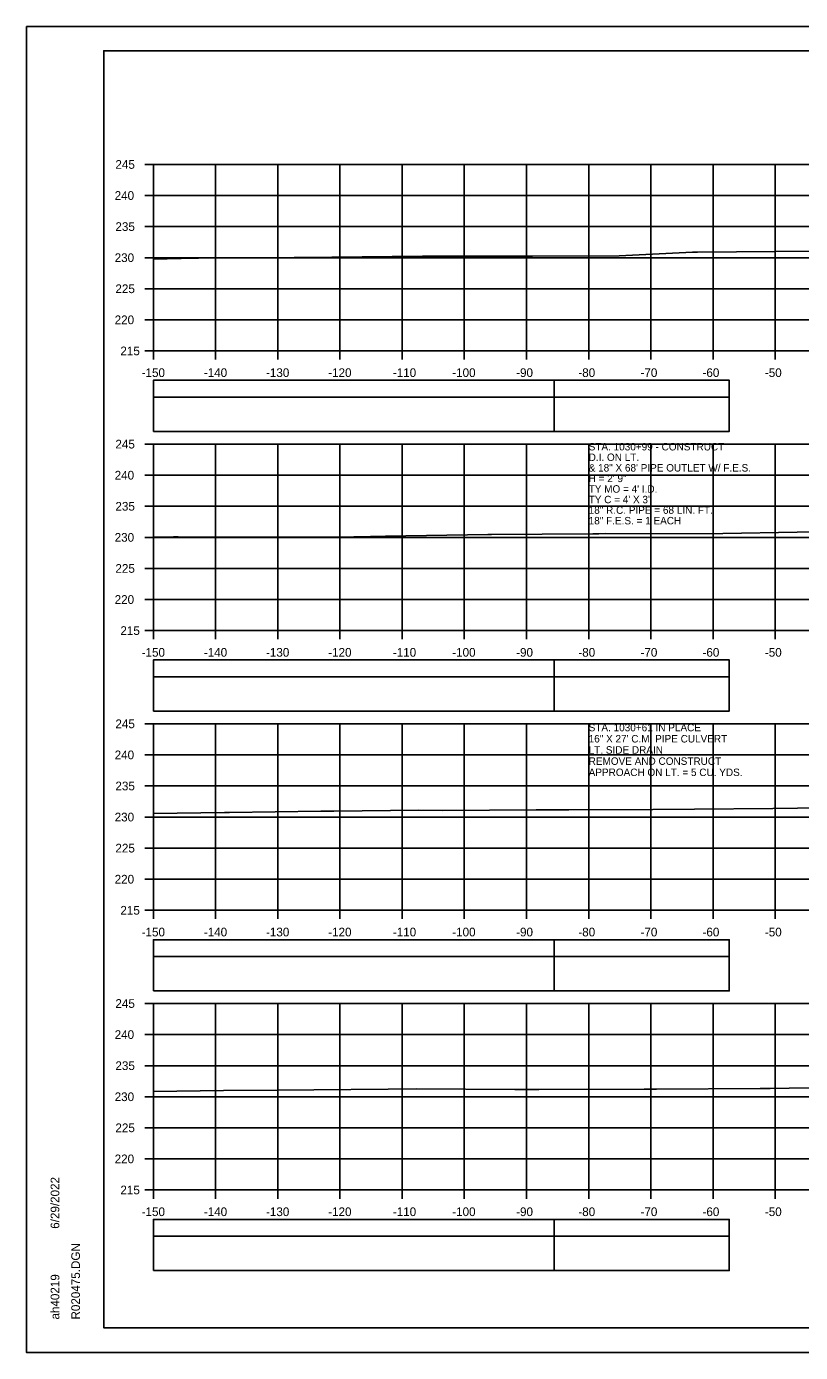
# Model space of a CAD drawing. Extents: x 1386544 to 1388153, y 379785 to 390999.
# Drawn here: x 1387177.5 to 1387301.9, y 385001.6 to 385214.9 of the extents above; entities that cross this region are included whole.
import ezdxf

# ---------------------------------------------------------------- set-up
doc = ezdxf.new("R2010")
doc.units = 0
for name, color, linetype in [('R_Axis', 7, 'Continuous'), ('R_Axis Annot', 7, 'Continuous'), ('R_Border', 7, 'Continuous'), ('R_Drive', 7, 'Continuous'), ('R_Exist Surface', 7, 'Continuous'), ('R_Grid', 7, 'Continuous'), ('R_No Plot', 7, 'Continuous'), ('R_Striping', 7, 'Continuous'), ('R_Water Annot', 7, 'Continuous')]:
    doc.layers.add(name, color=color, linetype=linetype)

msp = doc.modelspace()

# ---------------------------------------------------------------- linework, layer by layer
at = {"layer": 'R_Axis'}
for p, q in [((1387196.48, 385192.7), (1387197.88, 385192.7)), ((1387197.88, 385162.7), (1387197.88, 385192.7)), ((1387196.48, 385187.7), (1387197.88, 385187.7)), ((1387196.48, 385182.7), (1387197.88, 385182.7)), ((1387196.48, 385177.7), (1387197.88, 385177.7)), ((1387196.48, 385172.7), (1387197.88, 385172.7)), ((1387196.48, 385167.7), (1387197.88, 385167.7)), ((1387196.48, 385162.7), (1387197.88, 385162.7)), ((1387197.88, 385162.7), (1387497.88, 385162.7)), ((1387197.88, 385161.3), (1387197.88, 385162.7)), ((1387207.88, 385161.3), (1387207.88, 385162.7)), ((1387217.88, 385161.3), (1387217.88, 385162.7)), ((1387227.88, 385161.3), (1387227.88, 385162.7)), ((1387237.88, 385161.3), (1387237.88, 385162.7)), ((1387247.88, 385161.3), (1387247.88, 385162.7)), ((1387257.88, 385161.3), (1387257.88, 385162.7)), ((1387267.88, 385161.3), (1387267.88, 385162.7)), ((1387277.88, 385161.3), (1387277.88, 385162.7)), ((1387287.88, 385161.3), (1387287.88, 385162.7)), ((1387297.88, 385161.3), (1387297.88, 385162.7)), ((1387196.48, 385147.7), (1387197.88, 385147.7)), ((1387197.88, 385117.7), (1387197.88, 385147.7)), ((1387196.48, 385142.7), (1387197.88, 385142.7)), ((1387196.48, 385137.7), (1387197.88, 385137.7)), ((1387196.48, 385132.7), (1387197.88, 385132.7)), ((1387196.48, 385127.7), (1387197.88, 385127.7)), ((1387196.48, 385122.7), (1387197.88, 385122.7)), ((1387196.48, 385117.7), (1387197.88, 385117.7)), ((1387197.88, 385117.7), (1387497.88, 385117.7)), ((1387197.88, 385116.3), (1387197.88, 385117.7)), ((1387207.88, 385116.3), (1387207.88, 385117.7)), ((1387217.88, 385116.3), (1387217.88, 385117.7)), ((1387227.88, 385116.3), (1387227.88, 385117.7)), ((1387237.88, 385116.3), (1387237.88, 385117.7)), ((1387247.88, 385116.3), (1387247.88, 385117.7)), ((1387257.88, 385116.3), (1387257.88, 385117.7)), ((1387267.88, 385116.3), (1387267.88, 385117.7)), ((1387277.88, 385116.3), (1387277.88, 385117.7)), ((1387287.88, 385116.3), (1387287.88, 385117.7)), ((1387297.88, 385116.3), (1387297.88, 385117.7)), ((1387196.48, 385102.7), (1387197.88, 385102.7)), ((1387197.88, 385072.7), (1387197.88, 385102.7)), ((1387196.48, 385097.7), (1387197.88, 385097.7)), ((1387196.48, 385092.7), (1387197.88, 385092.7)), ((1387196.48, 385087.7), (1387197.88, 385087.7)), ((1387196.48, 385082.7), (1387197.88, 385082.7)), ((1387196.48, 385077.7), (1387197.88, 385077.7)), ((1387196.48, 385072.7), (1387197.88, 385072.7)), ((1387197.88, 385072.7), (1387497.88, 385072.7)), ((1387197.88, 385071.3), (1387197.88, 385072.7)), ((1387207.88, 385071.3), (1387207.88, 385072.7)), ((1387217.88, 385071.3), (1387217.88, 385072.7)), ((1387227.88, 385071.3), (1387227.88, 385072.7)), ((1387237.88, 385071.3), (1387237.88, 385072.7)), ((1387247.88, 385071.3), (1387247.88, 385072.7)), ((1387257.88, 385071.3), (1387257.88, 385072.7)), ((1387267.88, 385071.3), (1387267.88, 385072.7)), ((1387277.88, 385071.3), (1387277.88, 385072.7)), ((1387287.88, 385071.3), (1387287.88, 385072.7)), ((1387297.88, 385071.3), (1387297.88, 385072.7)), ((1387196.48, 385057.7), (1387197.88, 385057.7)), ((1387197.88, 385027.7), (1387197.88, 385057.7)), ((1387196.48, 385052.7), (1387197.88, 385052.7)), ((1387196.48, 385047.7), (1387197.88, 385047.7)), ((1387196.48, 385042.7), (1387197.88, 385042.7)), ((1387196.48, 385037.7), (1387197.88, 385037.7)), ((1387196.48, 385032.7), (1387197.88, 385032.7)), ((1387196.48, 385027.7), (1387197.88, 385027.7)), ((1387197.88, 385027.7), (1387497.88, 385027.7)), ((1387197.88, 385026.3), (1387197.88, 385027.7)), ((1387207.88, 385026.3), (1387207.88, 385027.7)), ((1387217.88, 385026.3), (1387217.88, 385027.7)), ((1387227.88, 385026.3), (1387227.88, 385027.7)), ((1387237.88, 385026.3), (1387237.88, 385027.7)), ((1387247.88, 385026.3), (1387247.88, 385027.7)), ((1387257.88, 385026.3), (1387257.88, 385027.7)), ((1387267.88, 385026.3), (1387267.88, 385027.7)), ((1387277.88, 385026.3), (1387277.88, 385027.7)), ((1387287.88, 385026.3), (1387287.88, 385027.7)), ((1387297.88, 385026.3), (1387297.88, 385027.7))]:
    msp.add_line(p, q, dxfattribs=at)
at = {"layer": 'R_Axis Annot'}
for points in [[(1387197.88, 385155.26), (1387262.32, 385155.26), (1387262.32, 385157.97), (1387197.88, 385157.97)], [(1387197.88, 385149.73), (1387262.32, 385149.73), (1387262.32, 385155.26), (1387197.88, 385155.26)], [(1387197.88, 385110.26), (1387262.32, 385110.26), (1387262.32, 385112.97), (1387197.88, 385112.97)], [(1387197.88, 385104.73), (1387262.32, 385104.73), (1387262.32, 385110.26), (1387197.88, 385110.26)], [(1387197.88, 385065.26), (1387262.32, 385065.26), (1387262.32, 385067.97), (1387197.88, 385067.97)], [(1387197.88, 385059.73), (1387262.32, 385059.73), (1387262.32, 385065.26), (1387197.88, 385065.26)], [(1387197.88, 385020.26), (1387262.32, 385020.26), (1387262.32, 385022.97), (1387197.88, 385022.97)], [(1387197.88, 385014.73), (1387262.32, 385014.73), (1387262.32, 385020.26), (1387197.88, 385020.26)]]:
    msp.add_lwpolyline(points, close=True, dxfattribs=at)
at = {"layer": 'R_Border'}
for p, q in [((1387189.88, 385211), (1387506.06, 385211)), ((1387189.88, 385005.54), (1387189.88, 385211)), ((1387189.88, 385005.54), (1387189.88, 385005.54)), ((1387506.06, 385005.54), (1387189.88, 385005.54))]:
    msp.add_line(p, q, dxfattribs=at)
at = {"layer": 'R_Exist Surface'}
for points in [[(1387197.88, 385177.46), (1387204.52, 385177.61), (1387205.14, 385177.62), (1387220.49, 385177.72), (1387220.57, 385177.72), (1387226.6, 385177.79), (1387241.14, 385177.96), (1387241.48, 385177.96), (1387257.69, 385177.95), (1387258.12, 385177.95), (1387258.82, 385177.96), (1387272.76, 385178), (1387284.56, 385178.59), (1387285.38, 385178.59), (1387304.16, 385178.74)], [(1387197.88, 385132.71), (1387201.09, 385132.78), (1387201.84, 385132.8), (1387220.62, 385132.71), (1387221.03, 385132.71), (1387230.09, 385132.81), (1387230.3, 385132.81), (1387235.23, 385132.89), (1387251.65, 385133.15), (1387252.24, 385133.16), (1387268.57, 385133.29), (1387269.52, 385133.28), (1387270.54, 385133.3), (1387287.89, 385133.28), (1387289.44, 385133.32), (1387301.4, 385133.53), (1387303.32, 385133.58)], [(1387197.88, 385088.26), (1387209.33, 385088.42), (1387210.1, 385088.42), (1387224.79, 385088.65), (1387226.9, 385088.67), (1387240.56, 385088.8), (1387244.44, 385088.78), (1387259.46, 385088.86), (1387264.7, 385088.87), (1387278.22, 385088.93), (1387284.9, 385088.97), (1387297.48, 385089.08), (1387305.43, 385089.17)], [(1387197.88, 385043.56), (1387201.65, 385043.58), (1387209.15, 385043.69), (1387218, 385043.74), (1387223.66, 385043.83), (1387235.66, 385043.92), (1387240.19, 385043.97), (1387256, 385043.87), (1387259.86, 385043.89), (1387276.78, 385043.91), (1387278.81, 385043.92), (1387295.47, 385044.03), (1387296.77, 385044.04), (1387297.07, 385044.04), (1387300.14, 385044.07), (1387316.34, 385044.27)]]:
    msp.add_lwpolyline(points, dxfattribs=at)
at = {"layer": 'R_Grid'}
for p, q in [((1387197.88, 385192.7), (1387497.88, 385192.7)), ((1387197.88, 385162.7), (1387197.88, 385192.7)), ((1387207.88, 385162.7), (1387207.88, 385192.7)), ((1387217.88, 385162.7), (1387217.88, 385192.7)), ((1387227.88, 385162.7), (1387227.88, 385192.7)), ((1387237.88, 385162.7), (1387237.88, 385192.7)), ((1387247.88, 385162.7), (1387247.88, 385192.7)), ((1387257.88, 385162.7), (1387257.88, 385192.7)), ((1387267.88, 385162.7), (1387267.88, 385192.7)), ((1387277.88, 385162.7), (1387277.88, 385192.7)), ((1387287.88, 385162.7), (1387287.88, 385192.7)), ((1387297.88, 385162.7), (1387297.88, 385192.7)), ((1387197.88, 385187.7), (1387497.88, 385187.7)), ((1387197.88, 385182.7), (1387497.88, 385182.7)), ((1387197.88, 385177.7), (1387497.88, 385177.7)), ((1387197.88, 385172.7), (1387497.88, 385172.7)), ((1387197.88, 385167.7), (1387497.88, 385167.7)), ((1387197.88, 385162.7), (1387497.88, 385162.7)), ((1387197.88, 385147.7), (1387497.88, 385147.7)), ((1387197.88, 385117.7), (1387197.88, 385147.7)), ((1387207.88, 385117.7), (1387207.88, 385147.7)), ((1387217.88, 385117.7), (1387217.88, 385147.7)), ((1387227.88, 385117.7), (1387227.88, 385147.7)), ((1387237.88, 385117.7), (1387237.88, 385147.7)), ((1387247.88, 385117.7), (1387247.88, 385147.7)), ((1387257.88, 385117.7), (1387257.88, 385147.7)), ((1387267.88, 385117.7), (1387267.88, 385147.7)), ((1387277.88, 385117.7), (1387277.88, 385147.7)), ((1387287.88, 385117.7), (1387287.88, 385147.7)), ((1387297.88, 385117.7), (1387297.88, 385147.7)), ((1387197.88, 385142.7), (1387497.88, 385142.7)), ((1387197.88, 385137.7), (1387497.88, 385137.7)), ((1387197.88, 385132.7), (1387497.88, 385132.7)), ((1387197.88, 385127.7), (1387497.88, 385127.7)), ((1387197.88, 385122.7), (1387497.88, 385122.7)), ((1387197.88, 385117.7), (1387497.88, 385117.7)), ((1387197.88, 385102.7), (1387497.88, 385102.7)), ((1387197.88, 385072.7), (1387197.88, 385102.7)), ((1387207.88, 385072.7), (1387207.88, 385102.7)), ((1387217.88, 385072.7), (1387217.88, 385102.7)), ((1387227.88, 385072.7), (1387227.88, 385102.7)), ((1387237.88, 385072.7), (1387237.88, 385102.7)), ((1387247.88, 385072.7), (1387247.88, 385102.7)), ((1387257.88, 385072.7), (1387257.88, 385102.7)), ((1387267.88, 385072.7), (1387267.88, 385102.7)), ((1387277.88, 385072.7), (1387277.88, 385102.7)), ((1387287.88, 385072.7), (1387287.88, 385102.7)), ((1387297.88, 385072.7), (1387297.88, 385102.7)), ((1387197.88, 385097.7), (1387497.88, 385097.7)), ((1387197.88, 385092.7), (1387497.88, 385092.7)), ((1387197.88, 385087.7), (1387497.88, 385087.7)), ((1387197.88, 385082.7), (1387497.88, 385082.7)), ((1387197.88, 385077.7), (1387497.88, 385077.7)), ((1387197.88, 385072.7), (1387497.88, 385072.7)), ((1387197.88, 385057.7), (1387497.88, 385057.7)), ((1387197.88, 385027.7), (1387197.88, 385057.7)), ((1387207.88, 385027.7), (1387207.88, 385057.7)), ((1387217.88, 385027.7), (1387217.88, 385057.7)), ((1387227.88, 385027.7), (1387227.88, 385057.7)), ((1387237.88, 385027.7), (1387237.88, 385057.7)), ((1387247.88, 385027.7), (1387247.88, 385057.7)), ((1387257.88, 385027.7), (1387257.88, 385057.7)), ((1387267.88, 385027.7), (1387267.88, 385057.7)), ((1387277.88, 385027.7), (1387277.88, 385057.7)), ((1387287.88, 385027.7), (1387287.88, 385057.7)), ((1387297.88, 385027.7), (1387297.88, 385057.7)), ((1387197.88, 385052.7), (1387497.88, 385052.7)), ((1387197.88, 385047.7), (1387497.88, 385047.7)), ((1387197.88, 385042.7), (1387497.88, 385042.7)), ((1387197.88, 385037.7), (1387497.88, 385037.7)), ((1387197.88, 385032.7), (1387497.88, 385032.7)), ((1387197.88, 385027.7), (1387497.88, 385027.7))]:
    msp.add_line(p, q, dxfattribs=at)
at = {"layer": 'R_No Plot'}
for p, q in [((1387177.48, 385214.89), (1387510.81, 385214.89)), ((1387177.48, 385001.56), (1387510.81, 385001.56))]:
    msp.add_line(p, q, dxfattribs=at)
for points in [[(1387177.47, 385214.89), (1387510.81, 385214.89), (1387510.81, 385001.55), (1387177.47, 385001.55)], [(1387423.8, 385211), (1387443.42, 385211), (1387443.42, 385201.12), (1387459.53, 385201.12), (1387482.73, 385201.12), (1387482.73, 385176.78), (1387506.06, 385176.78), (1387506.06, 385005.54), (1387189.88, 385005.54), (1387189.88, 385211)]]:
    msp.add_lwpolyline(points, close=True, dxfattribs=at)
at = {"layer": 'R_Striping'}
for points in [[(1387262.32, 385155.26), (1387290.5, 385155.26), (1387290.5, 385157.97), (1387262.32, 385157.97)], [(1387262.32, 385149.74), (1387290.5, 385149.74), (1387290.5, 385155.26), (1387262.32, 385155.26)], [(1387262.32, 385110.26), (1387290.5, 385110.26), (1387290.5, 385112.97), (1387262.32, 385112.97)], [(1387262.32, 385104.74), (1387290.5, 385104.74), (1387290.5, 385110.26), (1387262.32, 385110.26)], [(1387262.32, 385065.26), (1387290.5, 385065.26), (1387290.5, 385067.97), (1387262.32, 385067.97)], [(1387262.32, 385059.74), (1387290.5, 385059.74), (1387290.5, 385065.26), (1387262.32, 385065.26)], [(1387262.32, 385020.26), (1387290.5, 385020.26), (1387290.5, 385022.97), (1387262.32, 385022.97)], [(1387262.32, 385014.74), (1387290.5, 385014.74), (1387290.5, 385020.26), (1387262.32, 385020.26)]]:
    msp.add_lwpolyline(points, close=True, dxfattribs=at)

# ---------------------------------------------------------------- texts
at = {"layer": 'R_Axis Annot'}
for s, p in [('245', (1387191.77, 385192)), ('240', (1387191.65, 385187)), ('235', (1387191.77, 385182)), ('230', (1387191.65, 385177)), ('225', (1387191.77, 385172)), ('220', (1387191.65, 385167)), ('215', (1387192.57, 385162)), ('-150', (1387195.99, 385158.5)), ('-140', (1387205.99, 385158.5)), ('-130', (1387215.99, 385158.5)), ('-120', (1387225.99, 385158.5)), ('-110', (1387236.39, 385158.5)), ('-100', (1387245.94, 385158.5)), ('-90', (1387256.22, 385158.5)), ('-80', (1387266.22, 385158.5)), ('-70', (1387276.22, 385158.5)), ('-60', (1387286.19, 385158.5)), ('-50', (1387296.22, 385158.5)), ('245', (1387191.77, 385147)), ('240', (1387191.65, 385142)), ('235', (1387191.77, 385137)), ('230', (1387191.65, 385132)), ('225', (1387191.77, 385127)), ('220', (1387191.65, 385122)), ('215', (1387192.57, 385117)), ('-150', (1387195.99, 385113.5)), ('-140', (1387205.99, 385113.5)), ('-130', (1387215.99, 385113.5)), ('-120', (1387225.99, 385113.5)), ('-110', (1387236.39, 385113.5)), ('-100', (1387245.94, 385113.5)), ('-90', (1387256.22, 385113.5)), ('-80', (1387266.22, 385113.5)), ('-70', (1387276.22, 385113.5)), ('-60', (1387286.19, 385113.5)), ('-50', (1387296.22, 385113.5)), ('245', (1387191.77, 385102)), ('240', (1387191.65, 385097)), ('235', (1387191.77, 385092)), ('230', (1387191.65, 385087)), ('225', (1387191.77, 385082)), ('220', (1387191.65, 385077)), ('215', (1387192.57, 385072)), ('-150', (1387195.99, 385068.5)), ('-140', (1387205.99, 385068.5)), ('-130', (1387215.99, 385068.5)), ('-120', (1387225.99, 385068.5)), ('-110', (1387236.39, 385068.5)), ('-100', (1387245.94, 385068.5)), ('-90', (1387256.22, 385068.5)), ('-80', (1387266.22, 385068.5)), ('-70', (1387276.22, 385068.5)), ('-60', (1387286.19, 385068.5)), ('-50', (1387296.22, 385068.5)), ('245', (1387191.77, 385057)), ('240', (1387191.65, 385052)), ('235', (1387191.77, 385047)), ('230', (1387191.65, 385042)), ('225', (1387191.77, 385037)), ('220', (1387191.65, 385032)), ('215', (1387192.57, 385027)), ('-150', (1387195.99, 385023.5)), ('-140', (1387205.99, 385023.5)), ('-130', (1387215.99, 385023.5)), ('-120', (1387225.99, 385023.5)), ('-110', (1387236.39, 385023.5)), ('-100', (1387245.94, 385023.5)), ('-90', (1387256.22, 385023.5)), ('-80', (1387266.22, 385023.5)), ('-70', (1387276.22, 385023.5)), ('-60', (1387286.19, 385023.5)), ('-50', (1387296.22, 385023.5))]:
    msp.add_text(s, height=1.4, dxfattribs=at).set_placement(p)
at = {"layer": 'R_Border'}
for s, p in [('6/29/2022', (1387182.75, 385021.46)), ('R020475.DGN', (1387186.07, 385006.86)), ('ah40219', (1387182.75, 385006.86))]:
    msp.add_text(s, height=1.4, rotation=90, dxfattribs=at).set_placement(p)
at = {"layer": 'R_Drive'}
for s, p in [('STA. 1030+61 IN PLACE', (1387267.88, 385101.5)), ('16" X 27\' C.M. PIPE CULVERT', (1387267.88, 385099.7)), ('LT. SIDE DRAIN', (1387267.88, 385097.9)), ('REMOVE AND CONSTRUCT', (1387267.88, 385096.1)), ('APPROACH ON LT. = 5 CU. YDS.', (1387267.88, 385094.3))]:
    msp.add_text(s, height=1.2, dxfattribs=at).set_placement(p)
at = {"layer": 'R_Water Annot'}
for s, p in [('STA. 1030+99 - CONSTRUCT', (1387267.88, 385146.69)), ('D.I. ON LT.', (1387267.88, 385144.99)), ('& 18" X 68\' PIPE OUTLET W/ F.E.S.', (1387267.88, 385143.29)), ('H = 2\' 9"', (1387267.88, 385141.59)), ("TY MO = 4' I.D.", (1387267.88, 385139.89)), ("TY C = 4' X 3'", (1387267.88, 385138.19)), ('18" R.C. PIPE = 68 LIN. FT.', (1387267.88, 385136.49)), ('18" F.E.S. = 1 EACH', (1387267.88, 385134.79))]:
    msp.add_text(s, height=1.2, dxfattribs=at).set_placement(p)

doc.saveas('drawing.dxf')
